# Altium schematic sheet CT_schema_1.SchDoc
size 559 x 417 mm
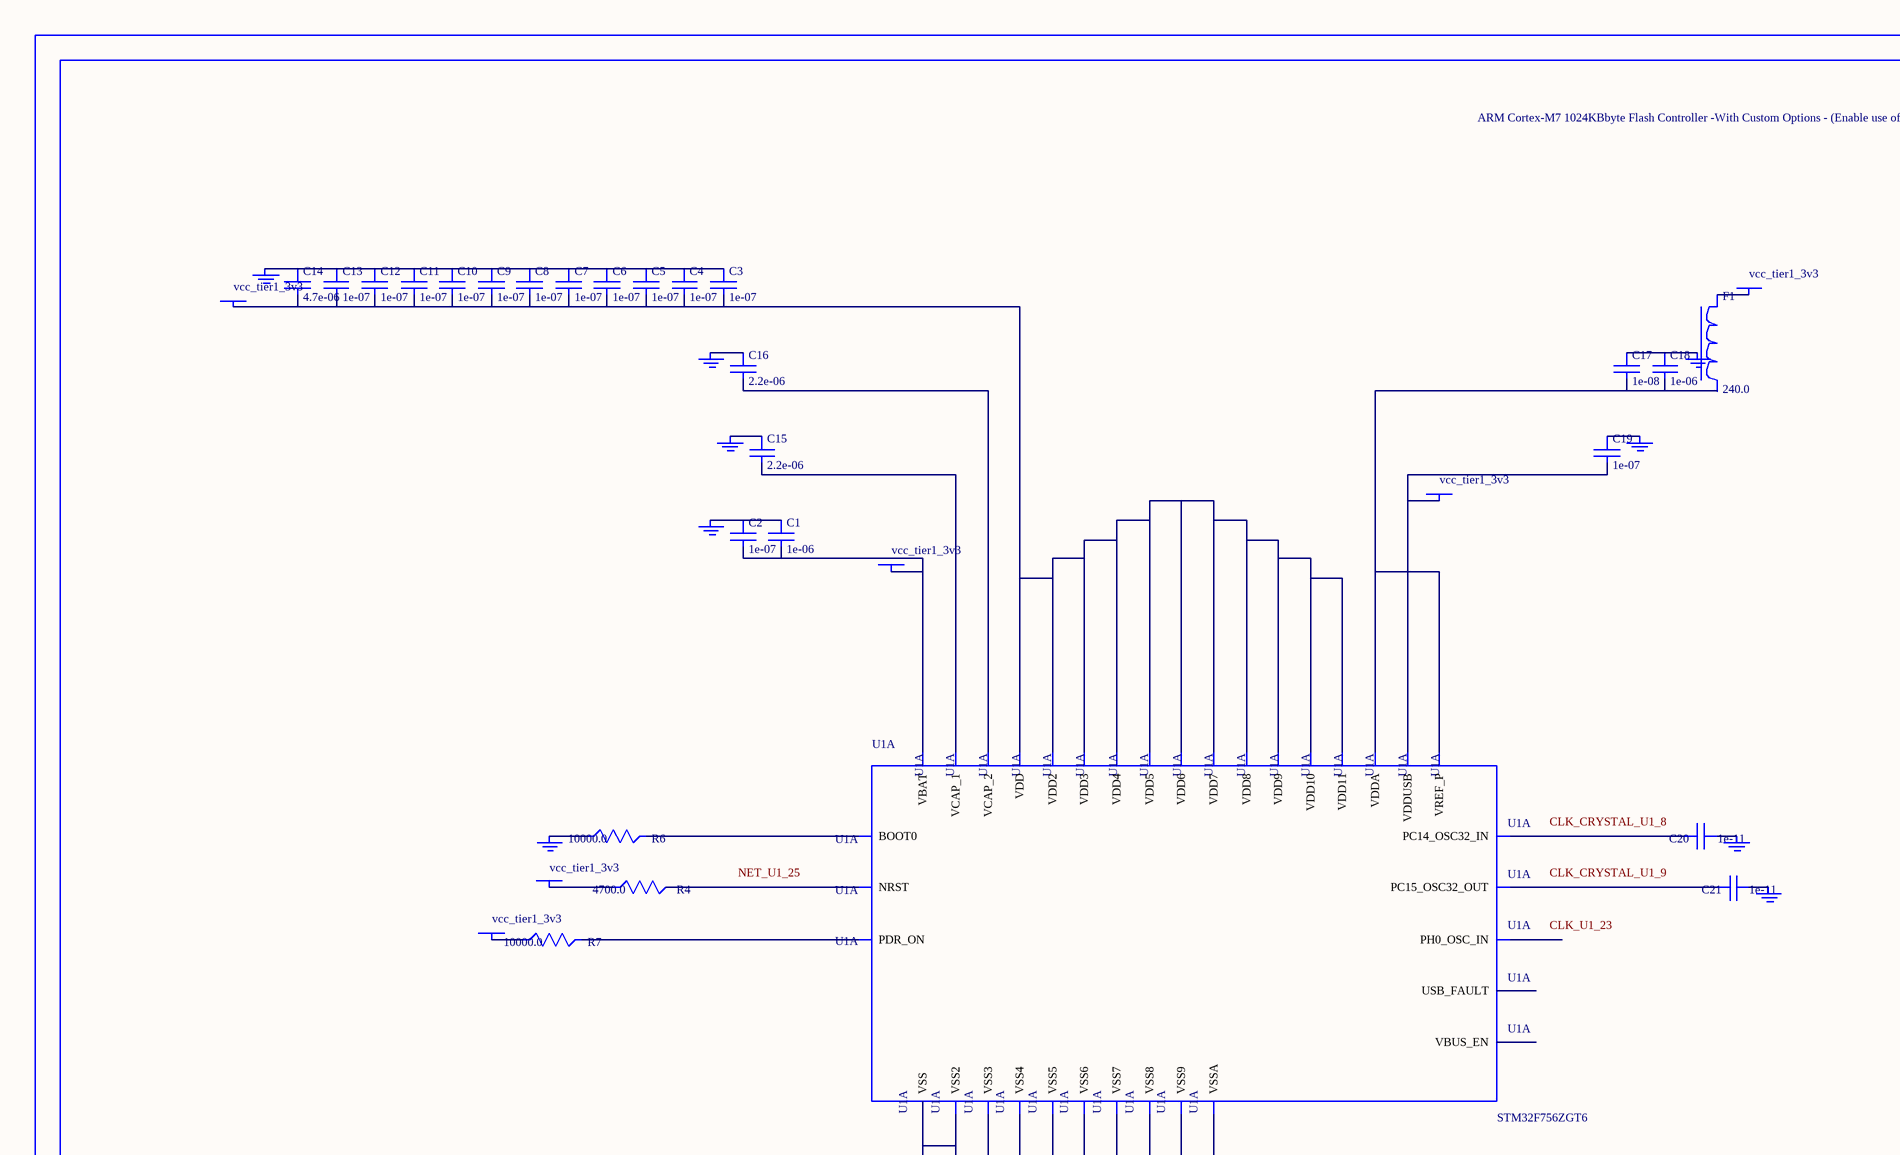
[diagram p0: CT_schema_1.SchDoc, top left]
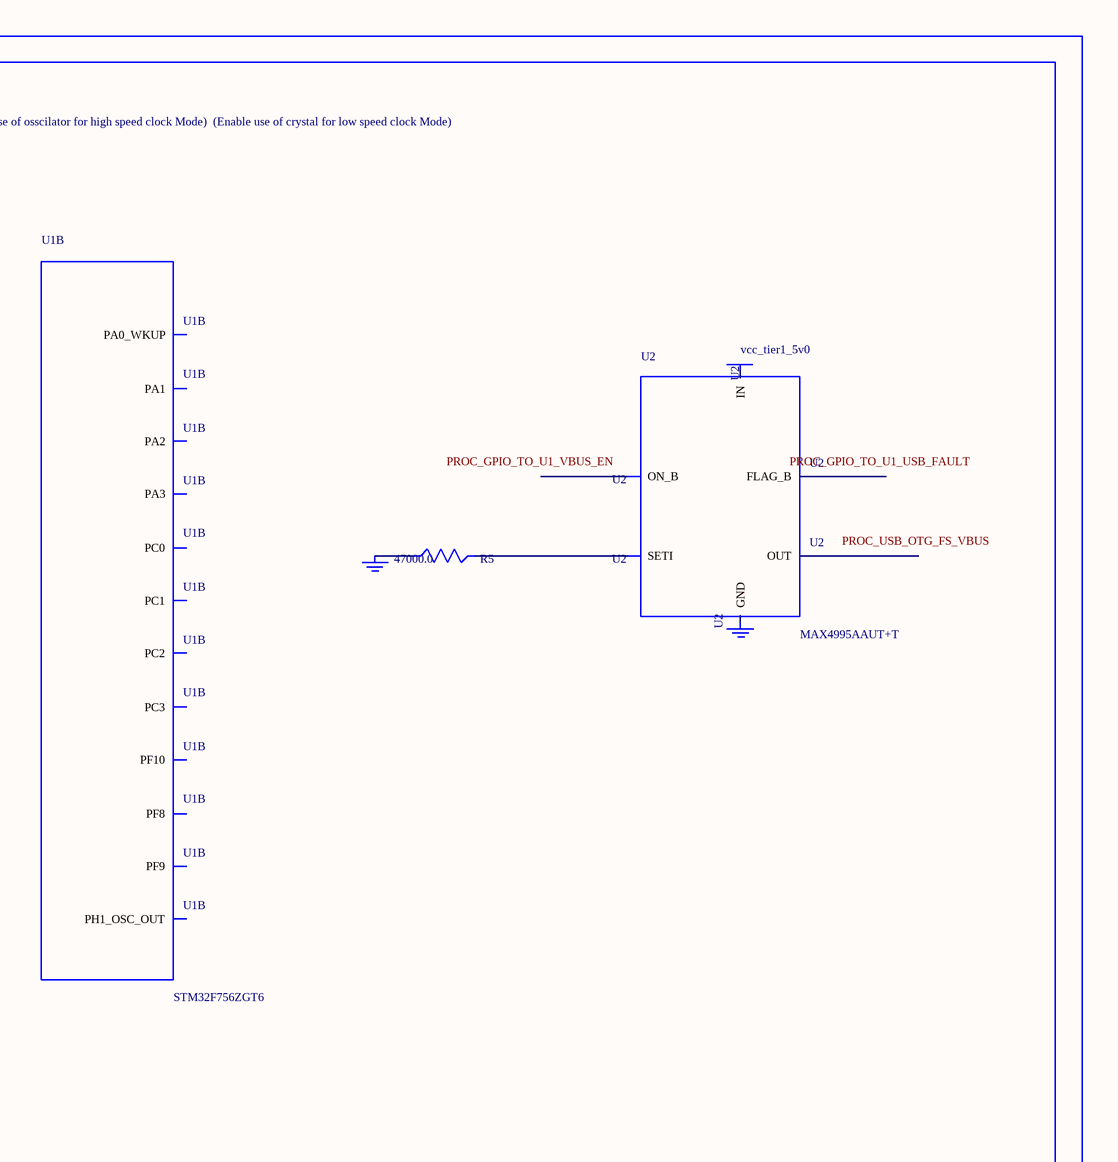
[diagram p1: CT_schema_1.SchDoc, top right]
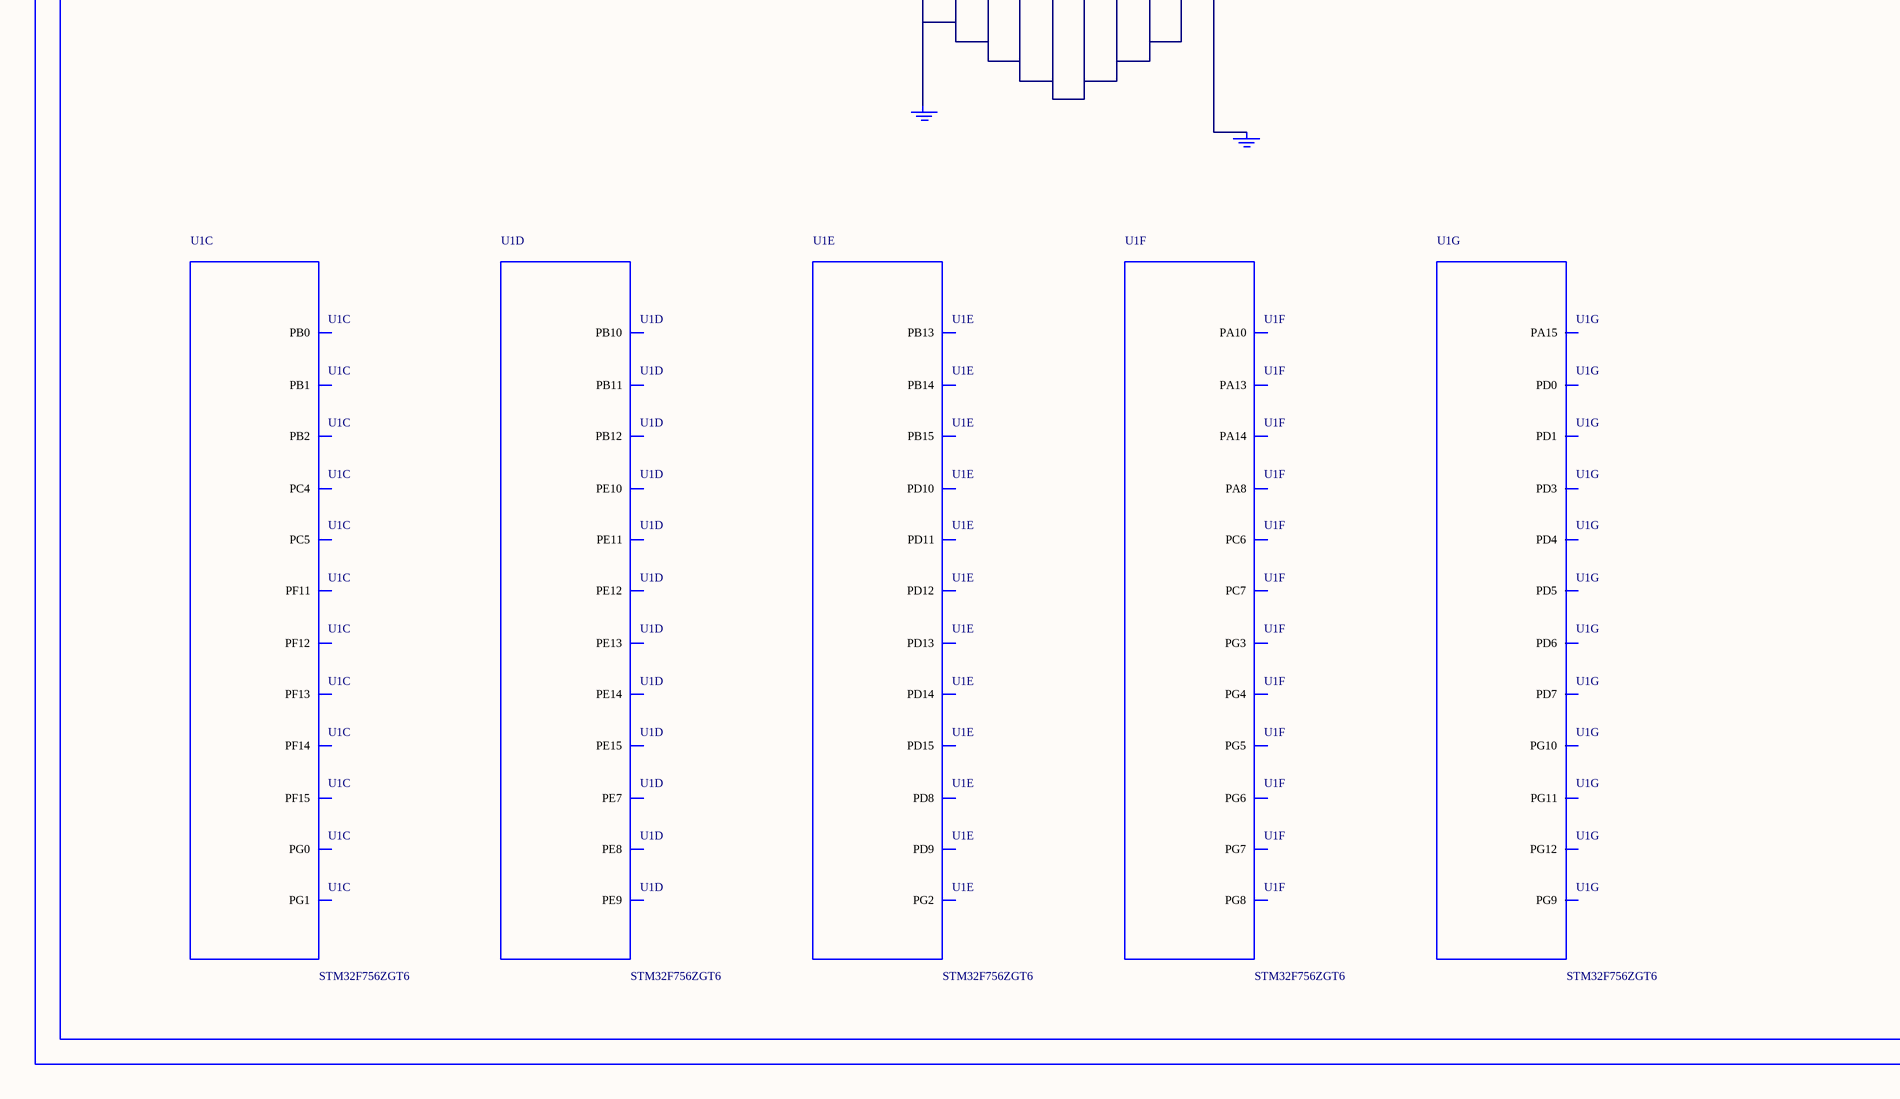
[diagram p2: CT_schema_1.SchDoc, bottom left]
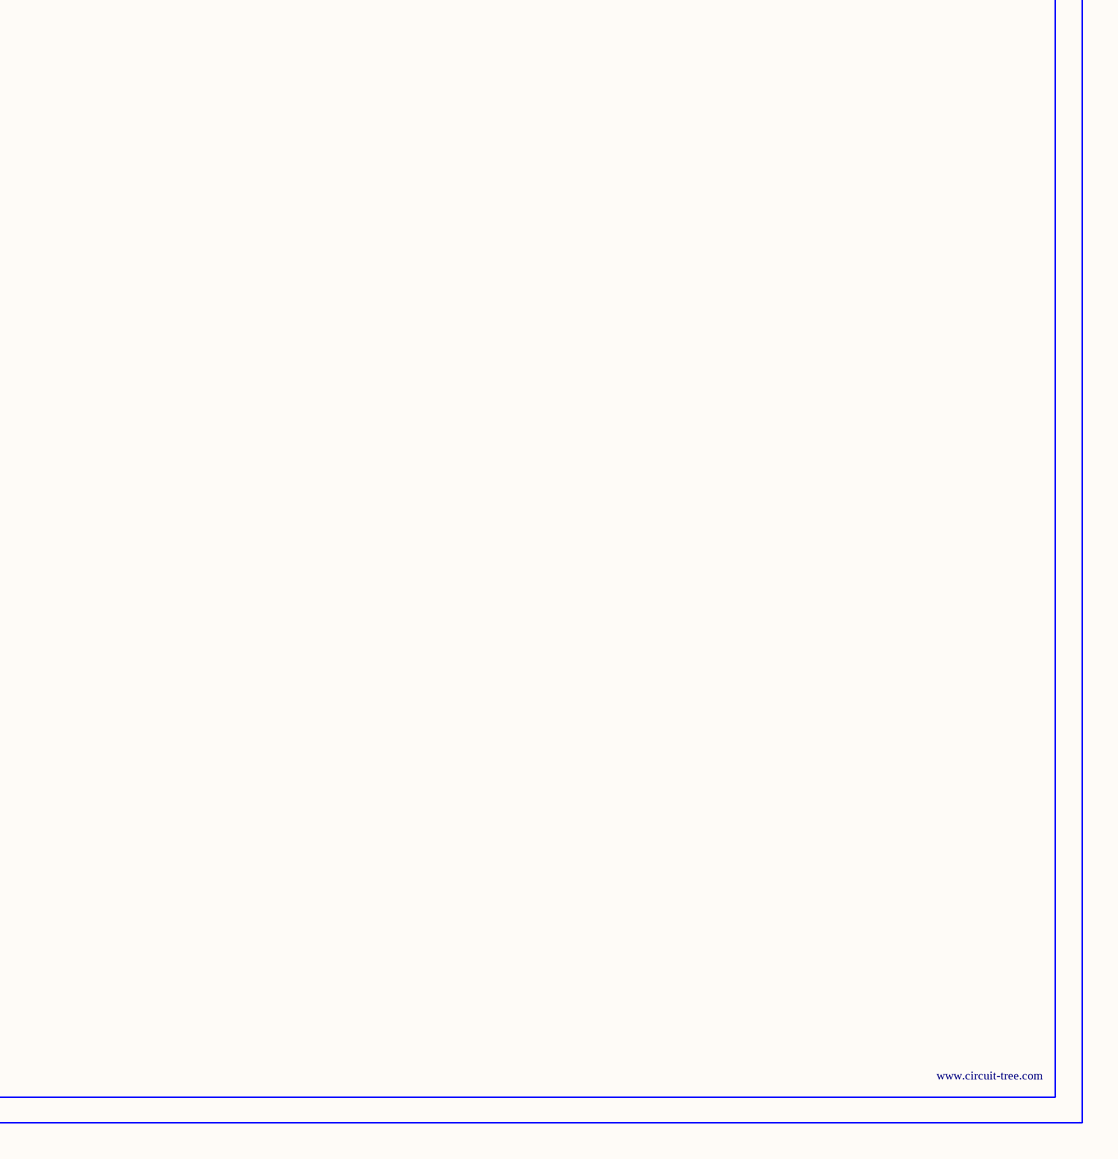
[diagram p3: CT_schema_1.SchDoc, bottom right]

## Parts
BORDER0  (no value)
C1  1e-06  [C0603]
C2  1e-07  [C0603]
C3  1e-07  [C0603]
C4  1e-07  [C0603]
C5  1e-07  [C0603]
C6  1e-07  [C0603]
C7  1e-07  [C0603]
C8  1e-07  [C0603]
C9  1e-07  [C0603]
C10  1e-07  [C0603]
C11  1e-07  [C0603]
C12  1e-07  [C0603]
C13  1e-07  [C0603]
C14  4.7e-06  [C0603]
C15  2.2e-06  [C0603]
C16  2.2e-06  [C0603]
C17  1e-08  [C0603]
C18  1e-06  [C0603]
C19  1e-07  [C0603]
C20  1e-11  [C0402]
C21  1e-11  [C0402]
F1  240.0  [L0603]
GND_INSTANCE_0_0  (no value)
GND_INSTANCE_0_1  (no value)
GND_INSTANCE_0_2  (no value)
GND_INSTANCE_0_3  (no value)
GND_INSTANCE_0_4  (no value)
GND_INSTANCE_0_5  (no value)
GND_INSTANCE_0_6  (no value)
GND_INSTANCE_0_7  (no value)
GND_INSTANCE_0_8  (no value)
GND_INSTANCE_0_9  (no value)
GND_INSTANCE_0_10  (no value)
GND_INSTANCE_0_11  (no value)
GND_INSTANCE_0_12  (no value)
POWER_INSTANCE_0_0  vcc_tier1_3v3
POWER_INSTANCE_0_1  vcc_tier1_3v3
POWER_INSTANCE_0_2  vcc_tier1_3v3
POWER_INSTANCE_0_3  vcc_tier1_3v3
POWER_INSTANCE_0_4  vcc_tier1_3v3
POWER_INSTANCE_0_5  vcc_tier1_3v3
POWER_INSTANCE_0_6  vcc_tier1_5v0
R4  4700.0  [R0603]
R5  47000.0  [R0603]
R6  10000.0  [R0603]
R7  10000.0  [R0603]
U1  STM32F756ZGT6  [LQFP144]  (parts A,B,C,D,E,F,G of 11)
U2  MAX4995AAUT+T  [SOT-23-6]

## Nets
NetC1_1: C1.1 C2.1 GND_INSTANCE_0_0.0(GND)
NetC1_2: C1.2 C2.2 POWER_INSTANCE_0_0.0(PWR) U1.6(VBAT)
NetC3_1: C3.1 C4.1 C5.1 C6.1 C7.1 C8.1 C9.1 C10.1 C11.1 C12.1 C13.1 C14.1 GND_INSTANCE_0_3.0(GND)
NetC3_2: C3.2 C4.2 C5.2 C6.2 C7.2 C8.2 C9.2 C10.2 C11.2 C12.2 C13.2 C14.2 POWER_INSTANCE_0_1.0(PWR) U1.17(VDD) U1.30(VDD2) U1.39(VDD3) U1.52(VDD4) U1.62(VDD5) U1.72(VDD6) U1.84(VDD7) U1.108(VDD8) U1.121(VDD9) U1.131(VDD10) U1.144(VDD11)
NetC15_1: C15.1 GND_INSTANCE_0_6.0(GND)
NetC15_2: C15.2 U1.71(VCAP_1)
NetC16_1: C16.1 GND_INSTANCE_0_8.0(GND)
NetC16_2: C16.2 U1.106(VCAP_2)
NetC17_1: C17.1 C18.1 GND_INSTANCE_0_5.0(GND)
NetC17_2: C17.2 C18.2 U1.32(VREF_P) U1.33(VDDA)
NetC19_1: C19.1 GND_INSTANCE_0_7.0(GND)
NetC19_2: C19.2 POWER_INSTANCE_0_3.0(PWR) U1.95(VDDUSB)
NetC20_1: C20.1 GND_INSTANCE_0_1.0(GND)
NetC20_2: C20.2 U1.8(PC14_OSC32_IN)
NetC21_1: C21.1 GND_INSTANCE_0_2.0(GND)
NetC21_2: C21.2 U1.9(PC15_OSC32_OUT)
NetF1_1: F1.1 POWER_INSTANCE_0_2.0(PWR)
NetGND_INSTANCE_0_4_0: GND_INSTANCE_0_4.0(GND) U1.31(VSSA)
NetGND_INSTANCE_0_9_0: GND_INSTANCE_0_9.0(GND) R6.1
NetGND_INSTANCE_0_10_0: GND_INSTANCE_0_10.0(GND) U1.16(VSS) U1.38(VSS2) U1.51(VSS3) U1.61(VSS4) U1.83(VSS5) U1.94(VSS6) U1.107(VSS7) U1.120(VSS8) U1.130(VSS9)
NetGND_INSTANCE_0_11_0: GND_INSTANCE_0_11.0(GND) R5.1
NetPOWER_INSTANCE_0_4_0: POWER_INSTANCE_0_4.0(PWR) R7.1
NetPOWER_INSTANCE_0_5_0: POWER_INSTANCE_0_5.0(PWR) R4.1
NetR4_2: R4.2 U1.25(NRST)
NetR5_2: R5.2 U2.3(SETI)
NetR6_2: R6.2 U1.138(BOOT0)
NetR7_2: R7.2 U1.143(PDR_ON)

Not connected (* = marked no-connect by the designer): F1 2; GND_INSTANCE_0_12 0(GND); POWER_INSTANCE_0_6 0(PWR); U1 1(VBUS_EN) 2(USB_FAULT) 20(PF8) 21(PF9) 22(PF10) 23(PH0_OSC_IN) 24(PH1_OSC_OUT) 26(PC0) 27(PC1) 28(PC2) 29(PC3) 34(PA0_WKUP) 35(PA1) 36(PA2) 37(PA3) 44(PC4) 45(PC5) 46(PB0) 47(PB1) 48(PB2) 49(PF11) 50(PF12) 53(PF13) 54(PF14) 55(PF15) 56(PG0) 57(PG1) 58(PE7) 59(PE8) 60(PE9) 63(PE10) 64(PE11) 65(PE12) 66(PE13) 67(PE14) 68(PE15) 69(PB10) 70(PB11) 73(PB12) 74(PB13) 75(PB14) 76(PB15) 77(PD8) 78(PD9) 79(PD10) 80(PD11) 81(PD12) 82(PD13) 85(PD14) 86(PD15) 87(PG2) 88(PG3) 89(PG4) 90(PG5) 91(PG6) 92(PG7) 93(PG8) 96(PC6) 97(PC7) 100(PA8) 102(PA10) 105(PA13) 109(PA14) 110(PA15) 114(PD0) 115(PD1) 117(PD3) 118(PD4) 119(PD5) 122(PD6) 123(PD7) 124(PG9) 125(PG10) 126(PG11) 127(PG12); U2 1(OUT) 2(GND) 4(ON_B) 5(IN) 6(FLAG_B)

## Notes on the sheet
- Labels drawn without touching a wire or pin: CLK_CRYSTAL_U1_8, CLK_CRYSTAL_U1_9, CLK_U1_23, NET_U1_25, PROC_GPIO_TO_U1_USB_FAULT, PROC_GPIO_TO_U1_VBUS_EN, PROC_USB_OTG_FS_VBUS

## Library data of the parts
BORDER0 = BORDER_PAGE0
C1 C18 = C0603C105K3RACTU
C2-C13 C19 = 06035C104K4Z2A
C14 = GRM188R6YA475KE15D
C15 C16 = C0603C225K8RACTU
C17 = 06035C103K4Z2A
C20 C21 = C0402C100K3GACTU
F1 = Z0603C241ASMST
GND_INSTANCE_0_0-GND_INSTANCE_0_12 = GND
POWER_INSTANCE_0_0-POWER_INSTANCE_0_6 = PWR
R4 = RC0603JR-074K7L
R5 = RC0603JR-0747KL
R6 R7 = RC0603JR-0710KL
